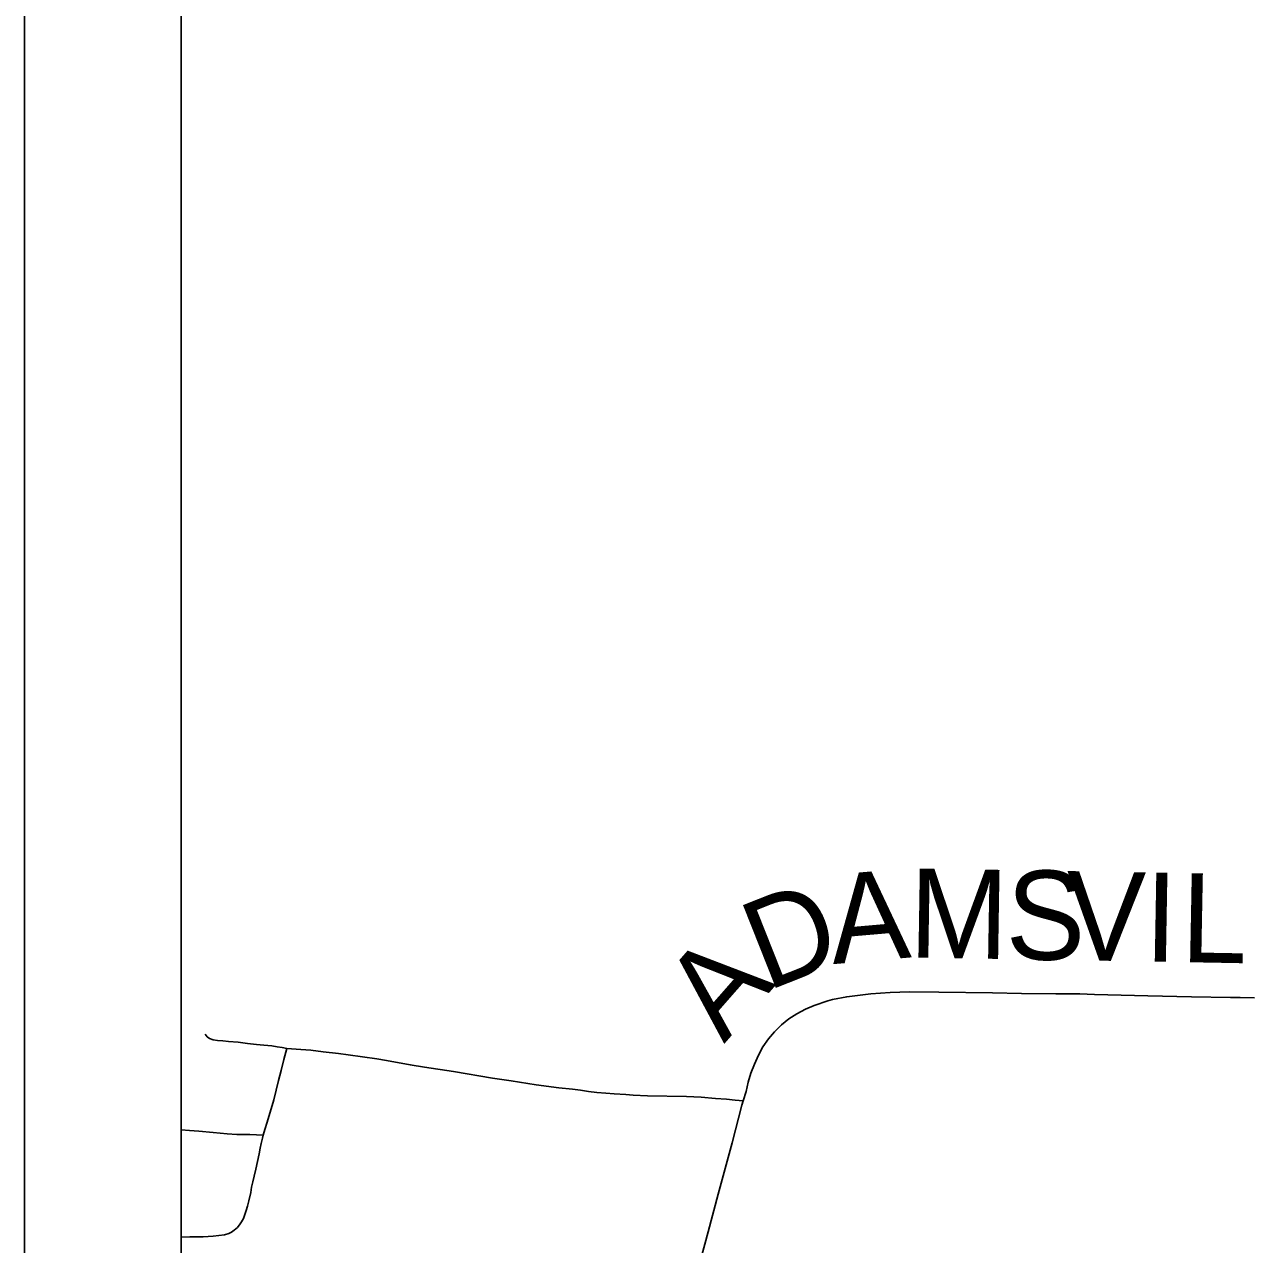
# Model space of a CAD drawing. Extents: x 0 to 34, y 0 to 22.
# Drawn here: x 2 to 2.781, y 16.863 to 17.641 of the extents above; entities that cross this region are included whole.
import ezdxf

# ---------------------------------------------------------------- set-up
doc = ezdxf.new("R2010")
doc.units = 0
for name, color, linetype in [('GM_X_County_Road', 7, 'Continuous'), ('GM_X_County_Road_Text', 7, 'Continuous'), ('GM_X_Rail_Line', 7, 'Continuous'), ('GM_X_Township_Road', 7, 'Continuous'), ('SH_Data', 7, 'Continuous')]:
    doc.layers.add(name, color=color, linetype=linetype)

msp = doc.modelspace()

# ---------------------------------------------------------------- linework, layer by layer
at = {"layer": 'GM_X_County_Road'}
for points in [[(2.45841, 16.95425), (2.46022, 16.96034), (2.46161, 16.96625), (2.46335, 16.97203), (2.46556, 16.97773), (2.4681, 16.98333), (2.47104, 16.9887), (2.47448, 16.99374), (2.47844, 16.9984), (2.4828, 17.00267), (2.48755, 17.00649), (2.49267, 17.00981), (2.49808, 17.01266), (2.50372, 17.01512), (2.5124, 17.01818), (2.51537, 17.0189), (2.52443, 17.02067), (2.53984, 17.02244), (2.55218, 17.02339), (2.56456, 17.02377), (2.58317, 17.02369), (2.61732, 17.02312), (2.63596, 17.02271), (2.65772, 17.02257), (2.67321, 17.02247), (2.68248, 17.02216), (2.71643, 17.02133), (2.74431, 17.0206), (2.76915, 17.02014), (2.77534, 17.0201), (2.78458, 17.01992)], [(2.42544, 16.83532), (2.42752, 16.84079), (2.43123, 16.85266), (2.43614, 16.87068), (2.44249, 16.89467), (2.45135, 16.92757), (2.4576, 16.95151), (2.45841, 16.95425)]]:
    msp.add_lwpolyline(points, dxfattribs=at)
at = {"layer": 'GM_X_Rail_Line'}
msp.add_lwpolyline([(2.1, 18.4819), (2.1, 15.41533), (3.91225, 15.33234), (3.94511, 15.33133), (3.97305, 15.32903), (4.01333, 15.32616), (4.02571, 15.32509), (4.03807, 15.32397), (4.07825, 15.32063), (4.10609, 15.31847), (4.17428, 15.31409), (4.18493, 15.31325), (4.19555, 15.31213), (4.19727, 15.31181), (5.10439, 15.27591), (5.24576, 15.271), (5.45222, 15.26384), (5.47898, 15.73095), (5.48211, 15.81891)], dxfattribs=at)
at = {"layer": 'GM_X_Township_Road'}
for points in [[(2.11521, 16.99691), (2.11661, 16.99506), (2.11807, 16.99398), (2.12042, 16.99322), (2.12316, 16.99277), (2.12659, 16.99252), (2.13009, 16.9922), (2.13619, 16.99169), (2.14229, 16.99093), (2.14808, 16.99029), (2.15265, 16.98985), (2.15771, 16.98927), (2.16121, 16.98872), (2.16437, 16.98822), (2.16731, 16.98776)], [(2.15218, 16.93231), (2.1533, 16.93591), (2.15488, 16.94078), (2.15896, 16.95498), (2.16199, 16.96716), (2.1637, 16.97373), (2.16541, 16.98058), (2.16731, 16.98776)], [(2.16731, 16.98776), (2.17632, 16.98704), (2.18257, 16.98654), (2.19056, 16.9856), (2.20033, 16.98441), (2.2065, 16.98364), (2.22471, 16.981), (2.23081, 16.98), (2.24605, 16.97734), (2.2552, 16.9757), (2.27363, 16.97297), (2.29842, 16.96875), (2.31045, 16.96709), (2.32629, 16.96454), (2.34073, 16.96252), (2.34947, 16.96164), (2.35469, 16.961), (2.35981, 16.96034), (2.36507, 16.95968), (2.37085, 16.95916), (2.37611, 16.95876), (2.3836, 16.95824), (2.3882, 16.95797), (2.39743, 16.95756), (2.42224, 16.95695), (2.43154, 16.95658), (2.44078, 16.95581), (2.44779, 16.95526), (2.45332, 16.95473), (2.45841, 16.95425)], [(2.1, 16.93582), (2.10521, 16.93541), (2.11131, 16.93486), (2.12035, 16.93404), (2.12935, 16.9333), (2.13536, 16.93292), (2.14377, 16.93271), (2.15218, 16.93231)], [(2.12761, 16.86882), (2.13031, 16.86962), (2.13211, 16.87052), (2.13373, 16.87172), (2.13577, 16.87352), (2.13757, 16.8758), (2.13847, 16.87712), (2.13967, 16.87934), (2.14057, 16.8818), (2.14141, 16.88426), (2.14225, 16.88702), (2.14317, 16.8904), (2.14432, 16.89582), (2.14488, 16.89928), (2.14561, 16.90269), (2.14647, 16.90623), (2.14752, 16.91062), (2.14962, 16.92053), (2.15041, 16.92408), (2.15106, 16.9271), (2.15175, 16.93055), (2.15218, 16.93231)], [(2.1, 16.86728), (2.10537, 16.86746), (2.11402, 16.86756), (2.12045, 16.86791), (2.12761, 16.86882)]]:
    msp.add_lwpolyline(points, dxfattribs=at)
at = {"layer": 'SH_Data'}
for p, q in [((2, 20.99996), (2, 13.99996)), ((2.1, 20.89996), (2.1, 14.09996))]:
    msp.add_line(p, q, dxfattribs=at)

# ---------------------------------------------------------------- texts
at = {"layer": 'GM_X_County_Road_Text'}
for s, rotation, p in [('A', 4.95301, (2.51566, 17.04145)), ('M', 359.0932, (2.56394, 17.04571)), ('S', 359.00692, (2.62558, 17.04473)), ('V', 359.00546, (2.66391, 17.04407)), ('I', 359.01247, (2.71391, 17.0432)), ('L', 358.93282, (2.73722, 17.0428)), ('D', 21.63433, (2.47343, 17.02401)), ('A', 48.76609, (2.44623, 16.99047))]:
    msp.add_text(s, height=0.05682, rotation=rotation, dxfattribs=at).set_placement(p)

doc.saveas('drawing.dxf')
